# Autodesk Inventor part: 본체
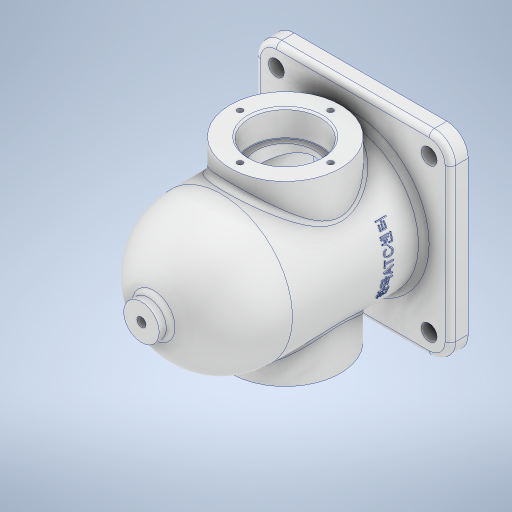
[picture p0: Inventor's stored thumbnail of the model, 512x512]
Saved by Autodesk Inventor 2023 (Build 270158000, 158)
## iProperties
Created: 2025-04
Part Number: 본체
Material: 알루미늄 6061
Document SubType Name: Modeling
Designer: ADMIN_PC
Density: 2.7 g/cm^3
Appearance: 알루미늄 - 평지
Mass: 865.906 g
Surface Area: 800.755 cm^2
Volume: 320.706 cm^3
Author: ADMIN_PC
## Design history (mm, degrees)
sketch "스케치1"
  geometry: C1 r 40 at (0, 0); 1 further point
  constraints: 1 centre point, 1 coincident
  dimensions: "d0" = 80 diameter of C1
extrude "돌출1" new body sketch "스케치1" stored distance "d1" = 84; taper "d2" = 0 deg
sketch "스케치2"
  geometry: L1 (55, 55)-(-55, 55); L2 (-55, 55)-(-55, -55); L3 (-55, -55)-(55, -55); L4 (55, -55)-(55, 55); L5 (55, 55)-(-55, -55); L6 (-55, 55)-(55, -55); 1 further point
  constraints: 12 end point, 2 midpoint, 2 parallel, 1 horizontal, 1 perpendicular
  dimensions: "d3" = 110 distance of L3.end L2.end; "d4" = 110 distance of L2.end L1.end
extrude "돌출2" join sketch "스케치2" distance "d5" = 10; taper "d6" = 0 deg
sketch "스케치4"
  geometry: C1 r 10 at (0, 0); 1 further point
  constraints: 1 centre point, 1 coincident
  dimensions: "d9" = 20 diameter of C1
extrude "돌출3" join sketch "스케치4" distance "d10" = 45; taper "d11" = 0 deg
sketch "스케치3"
  geometry: L1 (77, 0)-(-77, 0) reference; L2 (0, -58.8)-(0, 58.8) reference; L3 (40, 42)-(-40, 42) reference; L4 (40, 42)-(0, 42); L5 (0, 42)-(0, 82); A1 r 40 centre (0, 42) between (40, 42) and (0, 82); 1 further point
  constraints: 4 end point, 2 point on circle, 1 centre point, 1 collinear, 1 midpoint, 1 perpendicular, 1 point on line
  dimensions: "d8" = 40 radius of A1
revolve "회전1" sketch "스케치3" stored, may be unused: angle "d12" = 90 deg
sketch "스케치8"
  geometry: L1 (-55, -42)-(55, -42) reference; L2 (0, -67.8)-(0, 112.8) reference; C1 r 31 at (0, 6)
  constraints: 1 centre point, 1 point on line
  dimensions: "d14" = 62 diameter of C1; "d17" = 48 distance from line of L1 C1.centre
extrude "돌출4" join sketch "스케치8" stored distance "d15" = 100; taper "d16" = 0 deg
sketch "스케치9"
  geometry: L1 (76.691, 6)-(-85.662, 6); L2 (55, -42)-(-55, -42) reference; L3 (0, -67.8)-(0, 112.8) reference; L4 (50, -25)-(50, 37) reference; L5 (50, 6)-(35, 6); L6 (35, 6)-(35, 26); L7 (35, 26)-(50, 26); L8 (50, 26)-(50, 6); L9 (35, 6)-(-35, 6); L10 (-35, 6)-(-35, 22.5); L11 (-35, 22.5)-(35, 22.5); L12 (35, 22.5)-(35, 6); L13 (-50, 37)-(-50, -25) reference; L14 (-35, 6)-(-50, 6); L15 (-50, 6)-(-50, 26); L16 (-50, 26)-(-35, 26); L17 (-35, 26)-(-35, 6); 3 further points
  constraints: 26 end point, 6 parallel, 4 horizontal, 3 perpendicular, 2 point on line, 2 symmetric about line, 1 midpoint
  dimensions: "d19" = 48 distance between parallel lines of L2 L1; "d20" = 15 distance of L6.end L7.end; "d21" = 40 diameter of L7 L1; "d22" = 33 diameter of L11 L1
revolve "회전2" sketch "스케치9" stored, may be unused: angle "d23" = 90 deg
sketch "스케치10"
  geometry: C1 r 32 at (0, 0); 1 further point
  constraints: 1 centre point, 1 coincident
  dimensions: "d24" = 64 diameter of C1
extrude "돌출5" cut sketch "스케치10" distance "d25" = 84; taper "d26" = 0 deg
sketch "스케치11"
  geometry: L1 (32, 42)-(-32, 42) reference; L2 (-32, 42)-(0, 42); L3 (0, 74)-(0, 42); L4 (0, -67.8)-(0, 112.8) reference; A1 r 32 centre (0, 42) between (0, 74) and (-32, 42); 1 further point
  constraints: 4 end point, 2 point on circle, 1 centre point, 1 horizontal, 1 midpoint, 1 perpendicular
  dimensions: "d27" = 32 radius of A1
revolve "회전3" sketch "스케치11" stored, may be unused: angle "d28" = 90 deg
sketch "스케치12"
  geometry: C1 r 10 at (0, 0) reference; 2 further points
  constraints: 1 coincident
hole "구멍1" sketch "스케치12" at (0, 0) diameter "d29" = 5.1881; stored, may be unused: countersink angle "d33" = 90 deg, drill point angle "d35" = 0 deg; dims "d30" = 30, "d31" = 12, "d32" = 5, "d34" = 16
sketch "스케치13"
  geometry: L1 (0, 73.8)-(0, -106.8) reference; C1 r 20 at (0, 0) reference; 2 further points
  constraints: 1 point on line
  dimensions: "d36" = 25.5 distance of point (0, -25.5) C1.centre
hole "구멍2" sketch "스케치13" at (0, -25.5) diameter "d37" = 3.242; stored, may be unused: countersink angle "d41" = 90 deg, drill point angle "d43" = 118 deg; dims "d38" = 8, "d39" = 4, "d40" = 2, "d42" = 10
sketch "스케치14"
  geometry: L1 (55, 55)-(-55, 55) reference; L2 (-55, 55)-(-55, -55) reference; 2 further points
  dimensions: "d47" = 12 distance from line of L1 point (-43, 43); "d48" = 12 distance from line of L2 point (-43, 43)
hole "구멍3" sketch "스케치14" at (-43, 43) diameter "d49" = 9; stored, may be unused: countersink angle "d53" = 90 deg, drill point angle "d55" = 118 deg; dims "d50" = 8, "d51" = 4, "d52" = 2, "d54" = 10
chamfer "모따기1" distance "d62" = 1; stored, may be unused: second distance "d63" = 2, angle "d64" = 45 deg
fillet "모깎기1" dims "d65" = 0.3
fillet "모깎기2" dims "d66" = 12
fillet "모깎기3" dims "d67" = 3
node "작업 평면1"
sketch "스케치15"
  geometry: L1 (0, -67.8)-(0, 112.8) reference; L2 (43, -42)-(-43, -42) reference; 2 further points
  constraints: 1 point on line, 1 other
  dimensions: "d69" = 30 distance from line of L2 point (0, -12)
feature "엠보싱1" sketch "스케치15" dims "d70" = 0.5, "d71" = 0
feature "̩耀̫耀̭耀̯耀̱耀̳耀̵耀̷耀" dims "d0" = 80, "d1" = 84, "d2" = 0, "d3" = 110, "d4" = 110, "d5" = 10, "d6" = 0, "d8" = 40, "d9" = 20, "d10" = 45, "d11" = 0, "d12" = 90 deg, "d14" = 62, "d15" = 100, "d16" = 0, "d17" = 48, "d19" = 48, "d20" = 15, "d21" = 40, "d22" = 33, "d23" = 90 deg, "d24" = 64, "d25" = 84, "d26" = 0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
node "솔리드1"
pattern_circular "원형 패턴1" dims angle "d45" = 360 deg
mirror "미러1"
pattern_linear "직사각형 패턴1" dims "d58" = 86, "d61" = 86
feature "A9D066F2-1C7D-4E18-AEED-F7BC21143FA4" dims "d49" = 9, "d50" = 8, "d51" = 4, "d52" = 2, "d53" = 90 deg, "d54" = 10, "d55" = 118 deg
